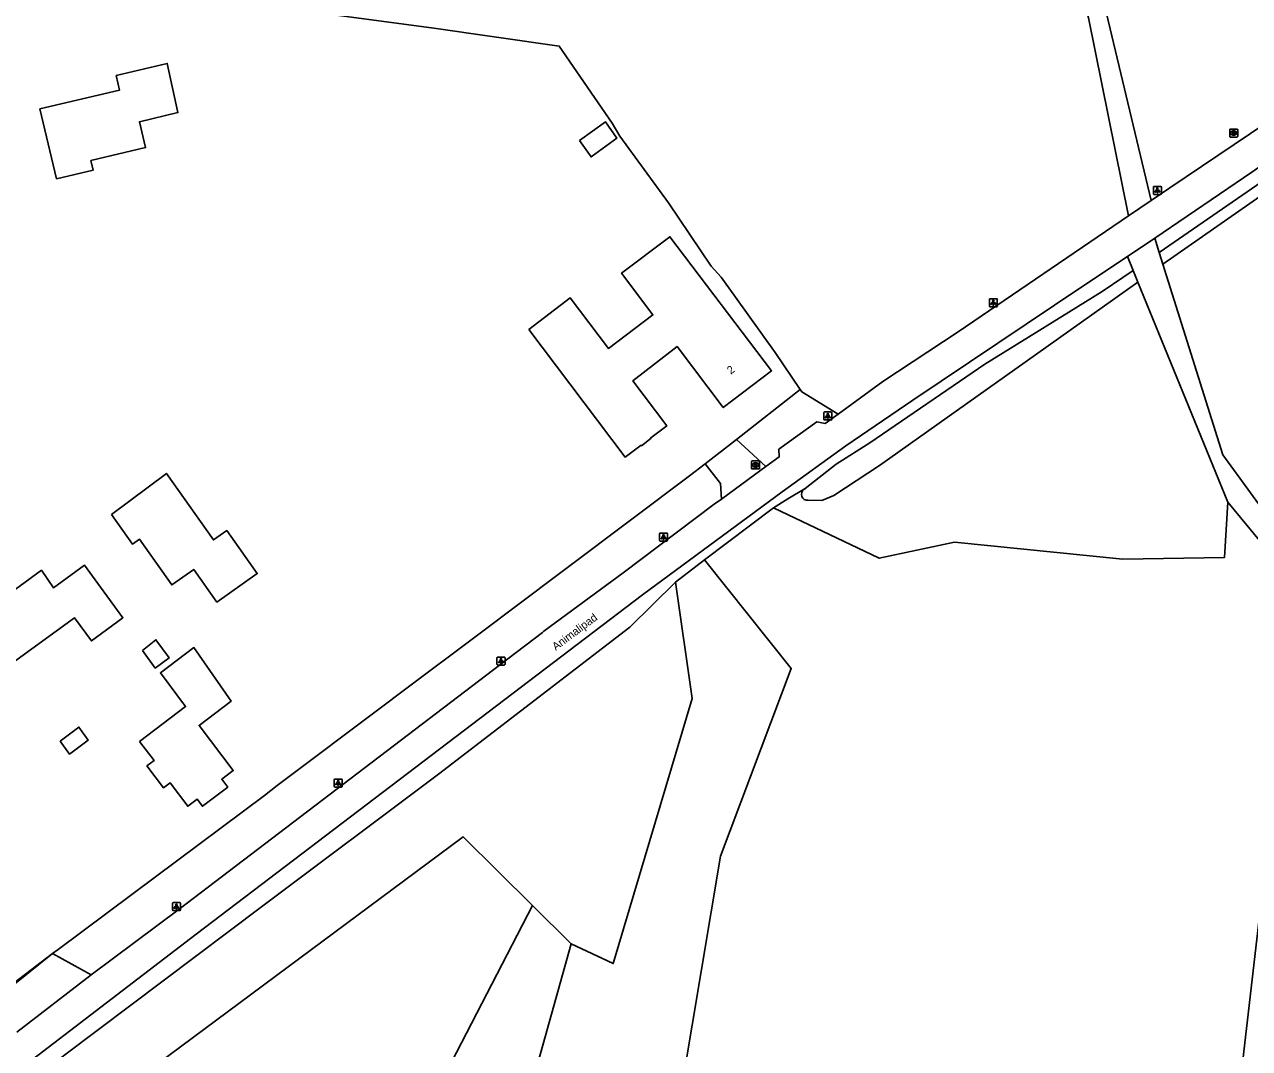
# Model space of a CAD drawing. Extents: x 162157 to 163165, y 378998 to 380775.
# Drawn here: x 162373.7 to 162526.7, y 380232.3 to 380360.2 of the extents above; entities that cross this region are included whole.
import ezdxf

# ---------------------------------------------------------------- set-up
doc = ezdxf.new("R2010")
doc.units = 0
for name, color, linetype in [('IMGEO_Berm_groen', 7, 'Continuous'), ('IMGEO_Brandkraan', 7, 'Continuous'), ('IMGEO_Grasland_overig', 7, 'Continuous'), ('IMGEO_Groenvoorziening', 7, 'Continuous'), ('IMGEO_Hek', 7, 'Continuous'), ('IMGEO_Lichtpunt', 7, 'Continuous'), ('IMGEO_Loofbos', 7, 'Continuous'), ('IMGEO_Muur', 7, 'Continuous'), ('IMGEO_Openbare_ruimte_label', 7, 'Continuous'), ('IMGEO_Pand', 7, 'Continuous'), ('IMGEO_Pand_nummerreeks', 7, 'Continuous'), ('IMGEO_Pand_vergunning_verleend', 7, 'Continuous'), ('IMGEO_Rijbaan_lokaal_gesloten', 7, 'Continuous'), ('IMGEO_Rijbaan_lokaal_halfverhard', 7, 'Continuous'), ('IMGEO_Voetpad_halfverhard', 7, 'Continuous'), ('IMGEO_Voetpad_open', 7, 'Continuous'), ('IMGEO_Waterloop', 7, 'Continuous')]:
    doc.layers.add(name, color=color, linetype=linetype)

msp = doc.modelspace()

# ---------------------------------------------------------------- linework, layer by layer
at = {"layer": 'IMGEO_Berm_groen'}
msp.add_lwpolyline([(162458.72, 380305.32), (162456.79, 380303.81), (162449.57, 380298.41), (162441.18, 380292.1), (162434.83, 380287.34), (162431.27, 380284.67), (162420.34, 380276.48), (162418.94, 380275.41), (162405.25, 380265.15), (162403.66, 380263.89), (162390.04, 380253.73), (162387.11, 380251.53), (162377.9, 380244.68), (162377.2, 380244.15)], dxfattribs=at)
at = {"layer": 'IMGEO_Brandkraan'}
for p, q in [((162524.26, 380346.2), (162524.26, 380347.05)), ((162524.33, 380347.13), (162525.19, 380347.13)), ((162525.19, 380346.13), (162524.33, 380346.13)), ((162524.75, 380346.91), (162524.77, 380346.91)), ((162524.77, 380346.35), (162524.75, 380346.35)), ((162525.26, 380347.05), (162525.26, 380346.2)), ((162464.53, 380304.76), (162464.53, 380305.61)), ((162464.61, 380305.68), (162465.46, 380305.68)), ((162465.02, 380305.46), (162465.05, 380305.46)), ((162465.04, 380304.9), (162465.02, 380304.9)), ((162465.53, 380305.61), (162465.53, 380304.76)), ((162465.46, 380304.68), (162464.61, 380304.68))]:
    msp.add_line(p, q, dxfattribs=at)
for points in [[(162524.26, 380346.2), (162524.26, 380347.05)], [(162524.33, 380347.13), (162525.19, 380347.13)], [(162525.19, 380346.13), (162524.33, 380346.13)], [(162524.61, 380346.83), (162524.61, 380346.43), (162524.82, 380346.43)], [(162524.84, 380346.83), (162524.61, 380346.83)], [(162524.79, 380346.75), (162524.73, 380346.75), (162524.73, 380346.67)], [(162524.73, 380346.67), (162524.79, 380346.67)], [(162524.8, 380346.59), (162524.73, 380346.59), (162524.73, 380346.51)], [(162524.73, 380346.51), (162524.8, 380346.51)], [(162525.26, 380347.05), (162525.26, 380346.2)], [(162464.53, 380304.76), (162464.53, 380305.61)], [(162464.61, 380305.68), (162465.46, 380305.68)], [(162464.88, 380305.38), (162464.88, 380304.98), (162465.09, 380304.98)], [(162465.11, 380305.38), (162464.88, 380305.38)], [(162465.06, 380305.3), (162465.01, 380305.3), (162465.01, 380305.22)], [(162465.01, 380305.22), (162465.06, 380305.22)], [(162465.07, 380305.15), (162465.01, 380305.15), (162465.01, 380305.07)], [(162465.01, 380305.07), (162465.07, 380305.07)], [(162465.53, 380305.61), (162465.53, 380304.76)], [(162465.46, 380304.68), (162464.61, 380304.68)]]:
    msp.add_lwpolyline(points, dxfattribs=at)
for centre, radius, start, end in [((162524.34, 380347.05), 0.0765, 91.552, 178.448), ((162524.34, 380347.05), 0.0765, 91.552, 178.448), ((162524.34, 380346.2), 0.0765, 181.552, 268.448), ((162524.34, 380346.2), 0.0765, 181.552, 268.448), ((162524.79, 380346.71), 0.0379, 267.8285, 90.9355), ((162524.8, 380346.55), 0.0404, 269.8759, 90.5077), ((162524.83, 380346.68), 0.251, 268.6676, 293.5347), ((162524.84, 380346.68), 0.145, 59.4692, 91.5367), ((162524.87, 380346.73), 0.0922, 285.5137, 58.1501), ((162524.87, 380346.54), 0.105, 301.3115, 78.989), ((162525.18, 380347.05), 0.0765, 1.552, 88.448), ((162525.18, 380347.05), 0.0765, 1.552, 88.448), ((162525.18, 380346.2), 0.0765, 271.552, 358.448), ((162525.18, 380346.2), 0.0765, 271.552, 358.448), ((162464.61, 380305.61), 0.0765, 91.552, 178.448), ((162464.61, 380305.61), 0.0765, 91.552, 178.448), ((162465.06, 380305.26), 0.0379, 267.8285, 90.9355), ((162465.07, 380305.11), 0.0404, 269.8759, 90.5077), ((162465.1, 380305.23), 0.251, 268.6676, 293.5347), ((162465.12, 380305.24), 0.145, 59.4692, 91.5367), ((162465.14, 380305.28), 0.0922, 285.5137, 58.1501), ((162465.15, 380305.09), 0.105, 301.3115, 78.989), ((162465.46, 380305.61), 0.0765, 1.552, 88.448), ((162465.46, 380305.61), 0.0765, 1.552, 88.448), ((162464.61, 380304.76), 0.0765, 181.552, 268.448), ((162464.61, 380304.76), 0.0765, 181.552, 268.448), ((162465.46, 380304.76), 0.0765, 271.552, 358.448), ((162465.46, 380304.76), 0.0765, 271.552, 358.448)]:
    msp.add_arc(centre, radius, start, end, dxfattribs=at)
for centre, major_axis, ratio, start_param, end_param in [((162524.75, 380346.63), (-0.387, 0.002), 0.722429, 4.712389, 7.853982), ((162524.77, 380346.63), (-0.39, 0.002), 0.717154, 1.570796, 4.712389), ((162465.02, 380305.18), (-0.387, 0.002), 0.722429, 4.712389, 7.853982), ((162465.04, 380305.18), (-0.39, 0.002), 0.717154, 1.570796, 4.712389)]:
    msp.add_ellipse(centre, major_axis=major_axis, ratio=ratio, start_param=start_param, end_param=end_param, dxfattribs=at)
at = {"layer": 'IMGEO_Grasland_overig'}
msp.add_lwpolyline([(162437.14, 380250.17), (162428.5, 380258.73), (162378.58, 380221.7), (162373.96, 380227.72)], dxfattribs=at)
at = {"layer": 'IMGEO_Groenvoorziening'}
for points in [[(162462.64, 380308.37), (162470.61, 380314.58)], [(162458.66, 380293.31), (162467.25, 380299.83)], [(162458.66, 380293.31), (162469.48, 380279.74), (162460.66, 380256.31), (162453.58, 380214.09), (162455.18, 380204.12), (162493.82, 380200.01), (162523.33, 380208.53)], [(162455.03, 380290.55), (162458.66, 380293.31)], [(162373.96, 380227.72), (162378.73, 380231.49), (162403.3, 380250), (162425.4, 380266.56), (162449.31, 380284.9), (162455.03, 380290.55)], [(162455.03, 380290.55), (162457.1, 380276), (162447.24, 380242.9), (162442, 380245.37)]]:
    msp.add_lwpolyline(points, dxfattribs=at)
at = {"layer": 'IMGEO_Hek'}
for points in [[(162470.61, 380314.58), (162467.48, 380319.24), (162460.73, 380328.61), (162459.47, 380329.99), (162454.14, 380337.89), (162448.06, 380346.22), (162447.12, 380347.84), (162440.5, 380357.48), (162424.53, 380359.77), (162327.51, 380372.72)], [(162470.8, 380314.29), (162470.61, 380314.58)], [(162377.2, 380244.15), (162372.39, 380240.52)], [(162377.9, 380244.68), (162377.2, 380244.15)]]:
    msp.add_lwpolyline(points, dxfattribs=at)
at = {"layer": 'IMGEO_Lichtpunt'}
for p, q in [((162514.73, 380339.87), (162514.73, 380339.06)), ((162514.73, 380339.87), (162514.73, 380339.06)), ((162515.64, 380339.96), (162514.83, 380339.96)), ((162515.64, 380339.96), (162514.83, 380339.96)), ((162514.83, 380338.97), (162515.64, 380338.97)), ((162514.83, 380338.97), (162515.64, 380338.97)), ((162515.73, 380339.06), (162515.73, 380339.87)), ((162515.73, 380339.06), (162515.73, 380339.87)), ((162494.24, 380325.84), (162494.24, 380325.03)), ((162494.24, 380325.84), (162494.24, 380325.03)), ((162495.14, 380325.93), (162494.33, 380325.93)), ((162495.14, 380325.93), (162494.33, 380325.93)), ((162494.33, 380324.94), (162495.14, 380324.94)), ((162494.33, 380324.94), (162495.14, 380324.94)), ((162495.23, 380325.03), (162495.23, 380325.84)), ((162495.23, 380325.03), (162495.23, 380325.84)), ((162473.55, 380311.69), (162473.55, 380310.88)), ((162473.55, 380311.69), (162473.55, 380310.88)), ((162474.45, 380311.79), (162473.65, 380311.79)), ((162474.45, 380311.79), (162473.65, 380311.79)), ((162474.55, 380310.88), (162474.55, 380311.69)), ((162474.55, 380310.88), (162474.55, 380311.69)), ((162473.65, 380310.79), (162474.45, 380310.79)), ((162473.65, 380310.79), (162474.45, 380310.79)), ((162453.03, 380296.57), (162453.03, 380295.76)), ((162453.03, 380296.57), (162453.03, 380295.76)), ((162453.93, 380296.66), (162453.12, 380296.66)), ((162453.93, 380296.66), (162453.12, 380296.66)), ((162453.12, 380295.67), (162453.93, 380295.67)), ((162453.12, 380295.67), (162453.93, 380295.67)), ((162454.03, 380295.76), (162454.03, 380296.57)), ((162454.03, 380295.76), (162454.03, 380296.57)), ((162432.72, 380281.09), (162432.72, 380280.29)), ((162432.72, 380281.09), (162432.72, 380280.29)), ((162433.62, 380281.19), (162432.82, 380281.19)), ((162433.62, 380281.19), (162432.82, 380281.19)), ((162433.72, 380280.29), (162433.72, 380281.09)), ((162433.72, 380280.29), (162433.72, 380281.09)), ((162432.82, 380280.19), (162433.62, 380280.19)), ((162432.82, 380280.19), (162433.62, 380280.19)), ((162412.38, 380265.85), (162412.38, 380265.05)), ((162412.38, 380265.85), (162412.38, 380265.05)), ((162413.28, 380265.95), (162412.47, 380265.95)), ((162413.28, 380265.95), (162412.47, 380265.95)), ((162413.37, 380265.05), (162413.37, 380265.85)), ((162413.37, 380265.05), (162413.37, 380265.85)), ((162412.47, 380264.95), (162413.28, 380264.95)), ((162412.47, 380264.95), (162413.28, 380264.95)), ((162392.17, 380250.42), (162392.17, 380249.62)), ((162392.17, 380250.42), (162392.17, 380249.62)), ((162393.07, 380250.52), (162392.27, 380250.52)), ((162393.07, 380250.52), (162392.27, 380250.52)), ((162393.17, 380249.62), (162393.17, 380250.42)), ((162393.17, 380249.62), (162393.17, 380250.42)), ((162392.27, 380249.52), (162393.07, 380249.52)), ((162392.27, 380249.52), (162393.07, 380249.52))]:
    msp.add_line(p, q, dxfattribs=at)
for points in [[(162515.11, 380339.53), (162515.15, 380339.5), (162514.96, 380339.24), (162514.92, 380339.27), (162515.11, 380339.53)], [(162515.21, 380339.48), (162515.26, 380339.48), (162515.26, 380339.16), (162515.21, 380339.16), (162515.21, 380339.48)], [(162515.32, 380339.5), (162515.36, 380339.53), (162515.54, 380339.27), (162515.51, 380339.24), (162515.32, 380339.5)], [(162494.61, 380325.5), (162494.65, 380325.47), (162494.46, 380325.21), (162494.42, 380325.24), (162494.61, 380325.5)], [(162494.71, 380325.45), (162494.76, 380325.45), (162494.76, 380325.13), (162494.71, 380325.13), (162494.71, 380325.45)], [(162494.82, 380325.47), (162494.86, 380325.5), (162495.05, 380325.24), (162495.01, 380325.21), (162494.82, 380325.47)], [(162473.93, 380311.35), (162473.96, 380311.33), (162473.78, 380311.06), (162473.74, 380311.09), (162473.93, 380311.35)], [(162474.03, 380311.31), (162474.08, 380311.31), (162474.08, 380310.98), (162474.03, 380310.98), (162474.03, 380311.31)], [(162474.14, 380311.33), (162474.18, 380311.35), (162474.36, 380311.09), (162474.32, 380311.06), (162474.14, 380311.33)], [(162453.4, 380296.23), (162453.44, 380296.2), (162453.25, 380295.94), (162453.22, 380295.97), (162453.4, 380296.23)], [(162453.5, 380296.18), (162453.55, 380296.18), (162453.55, 380295.86), (162453.5, 380295.86), (162453.5, 380296.18)], [(162453.61, 380296.2), (162453.65, 380296.23), (162453.84, 380295.97), (162453.8, 380295.94), (162453.61, 380296.2)], [(162433.1, 380280.76), (162433.13, 380280.73), (162432.95, 380280.47), (162432.91, 380280.5), (162433.1, 380280.76)], [(162433.2, 380280.71), (162433.24, 380280.71), (162433.24, 380280.39), (162433.2, 380280.39), (162433.2, 380280.71)], [(162433.31, 380280.73), (162433.35, 380280.76), (162433.53, 380280.49), (162433.49, 380280.47), (162433.31, 380280.73)], [(162412.75, 380265.52), (162412.79, 380265.49), (162412.6, 380265.23), (162412.56, 380265.25), (162412.75, 380265.52)], [(162412.85, 380265.47), (162412.9, 380265.47), (162412.9, 380265.15), (162412.85, 380265.15), (162412.85, 380265.47)], [(162412.96, 380265.49), (162413, 380265.52), (162413.19, 380265.25), (162413.15, 380265.23), (162412.96, 380265.49)], [(162392.55, 380250.09), (162392.58, 380250.06), (162392.4, 380249.8), (162392.36, 380249.82), (162392.55, 380250.09)], [(162392.65, 380250.04), (162392.69, 380250.04), (162392.69, 380249.72), (162392.65, 380249.72), (162392.65, 380250.04)], [(162392.76, 380250.06), (162392.8, 380250.09), (162392.98, 380249.82), (162392.94, 380249.8), (162392.76, 380250.06)]]:
    msp.add_lwpolyline(points, dxfattribs=at)
for centre in [(162515.23, 380339.67), (162494.74, 380325.64), (162474.05, 380311.49), (162453.53, 380296.37), (162433.22, 380280.89), (162412.88, 380265.65), (162392.67, 380250.22)]:
    msp.add_circle(centre, 0.0994, dxfattribs=at)
for centre, start, end in [((162514.83, 380339.87), 90, 180), ((162514.83, 380339.87), 90, 180), ((162514.83, 380339.06), 180, 270), ((162514.83, 380339.06), 180, 270), ((162515.64, 380339.87), 0, 90), ((162515.64, 380339.87), 0, 90), ((162515.64, 380339.06), 270, 0), ((162515.64, 380339.06), 270, 360), ((162494.33, 380325.84), 90, 180), ((162494.33, 380325.84), 90, 180), ((162494.33, 380325.03), 180, 270), ((162494.33, 380325.03), 180, 270), ((162495.14, 380325.84), 0, 90), ((162495.14, 380325.84), 0, 90), ((162495.14, 380325.03), 270, 0), ((162495.14, 380325.03), 270, 360), ((162473.65, 380311.69), 90, 180), ((162473.65, 380311.69), 90, 180), ((162474.45, 380311.69), 0, 90), ((162474.45, 380311.69), 0, 90), ((162473.65, 380310.88), 180, 270), ((162473.65, 380310.88), 180, 270), ((162474.45, 380310.88), 270, 0), ((162474.45, 380310.88), 270, 360), ((162453.12, 380296.57), 90, 180), ((162453.12, 380296.57), 90, 180), ((162453.12, 380295.76), 180, 270), ((162453.12, 380295.76), 180, 270), ((162453.93, 380296.57), 0, 90), ((162453.93, 380296.57), 0, 90), ((162453.93, 380295.76), 270, 0), ((162453.93, 380295.76), 270, 360), ((162432.82, 380281.09), 90, 180), ((162432.82, 380281.09), 90, 180), ((162432.82, 380280.29), 180, 270), ((162432.82, 380280.29), 180, 270), ((162433.62, 380281.09), 0, 90), ((162433.62, 380281.09), 0, 90), ((162433.62, 380280.29), 270, 0), ((162433.62, 380280.29), 270, 360), ((162412.47, 380265.85), 90, 180), ((162412.47, 380265.85), 90, 180), ((162412.47, 380265.05), 180, 270), ((162412.47, 380265.05), 180, 270), ((162413.28, 380265.85), 0, 90), ((162413.28, 380265.85), 0, 90), ((162413.28, 380265.05), 270, 0), ((162413.28, 380265.05), 270, 360), ((162392.27, 380250.42), 90, 180), ((162392.27, 380250.42), 90, 180), ((162393.07, 380250.42), 0, 90), ((162393.07, 380250.42), 0, 90), ((162392.27, 380249.62), 180, 270), ((162392.27, 380249.62), 180, 270), ((162393.07, 380249.62), 270, 0), ((162393.07, 380249.62), 270, 360)]:
    msp.add_arc(centre, 0.0946, start, end, dxfattribs=at)
at = {"layer": 'IMGEO_Loofbos'}
for points in [[(162252.22, 380382.98), (162295.98, 380377.02), (162327.51, 380372.72), (162424.53, 380359.77), (162440.5, 380357.48), (162447.12, 380347.84), (162448.06, 380346.22), (162454.14, 380337.89), (162459.47, 380329.99), (162460.73, 380328.61), (162467.48, 380319.24), (162470.61, 380314.58)], [(162470.61, 380314.58), (162470.8, 380314.29), (162475.36, 380311.53)], [(162467.25, 380299.83), (162469.05, 380300.96), (162471.22, 380302.25)], [(162467.25, 380299.83), (162480.48, 380293.52), (162489.86, 380295.52), (162510.9, 380293.43), (162523.61, 380293.6), (162524.04, 380300.51)], [(162523.33, 380208.53), (162532, 380283.39), (162532.68, 380288.65)], [(162437.14, 380250.17), (162411.8, 380201.13), (162369.04, 380207.47)], [(162442, 380245.37), (162437.14, 380250.17)], [(162523.33, 380208.53), (162520.84, 380187.03), (162441.69, 380197.08), (162430.3, 380203.52), (162442, 380245.37)]]:
    msp.add_lwpolyline(points, dxfattribs=at)
at = {"layer": 'IMGEO_Muur'}
for points in [[(162449.57, 380298.41), (162441.18, 380292.1)], [(162434.83, 380287.34), (162441.18, 380292.1)], [(162420.34, 380276.48), (162431.27, 380284.67)], [(162418.94, 380275.41), (162420.34, 380276.48)], [(162405.25, 380265.15), (162418.94, 380275.41)], [(162403.66, 380263.89), (162405.25, 380265.15)], [(162390.04, 380253.73), (162403.66, 380263.89)], [(162387.11, 380251.53), (162390.04, 380253.73)], [(162377.9, 380244.68), (162387.11, 380251.53)]]:
    msp.add_lwpolyline(points, dxfattribs=at)
at = {"layer": 'IMGEO_Pand'}
for points in [[(162443.04, 380345.68), (162446.27, 380348.03), (162447.71, 380345.99), (162444.48, 380343.64), (162443.04, 380345.68)], [(162436.69, 380322.11), (162441.87, 380326.03), (162446.64, 380319.72), (162452.21, 380323.92), (162448.29, 380329.11), (162454.33, 380333.67), (162467, 380316.93), (162460.98, 380312.34), (162455.22, 380319.96), (162449.68, 380315.67), (162453.92, 380310.05), (162451.93, 380308.57), (162451.98, 380308.51), (162450.79, 380307.57), (162450.73, 380307.65), (162448.72, 380306.16), (162436.69, 380322.11)]]:
    msp.add_lwpolyline(points, dxfattribs=at)
at = {"layer": 'IMGEO_Pand_vergunning_verleend'}
for points in [[(162375.62, 380349.63), (162385.57, 380351.99), (162385.14, 380353.81), (162391.53, 380355.33), (162392.86, 380349.18), (162388.05, 380348.04), (162388.81, 380344.81), (162381.98, 380343.19), (162382.27, 380342), (162377.69, 380340.91), (162375.62, 380349.63)], [(162384.55, 380298.98), (162391.42, 380304.11), (162397.29, 380295.81), (162398.96, 380296.99), (162402.76, 380291.62), (162397.73, 380288.06), (162394.84, 380292.14), (162392.09, 380290.2), (162388.07, 380295.89), (162387.18, 380295.27), (162384.55, 380298.98)], [(162366.96, 380285.57), (162375.8, 380292.03), (162377.31, 380289.82), (162381.19, 380292.66), (162385.98, 380286.09), (162382.04, 380283.21), (162379.93, 380286.1), (162371.4, 380279.87), (162370.38, 380281.26), (162369.53, 380280.64), (162367.31, 380283.68), (162367.98, 380284.17), (162366.96, 380285.57)], [(162388.41, 380282.01), (162390.11, 380283.34), (162391.76, 380281.08), (162390.02, 380279.81), (162388.41, 380282.01)], [(162388.06, 380270.66), (162393.82, 380275.01), (162390.66, 380279.21), (162394.86, 380282.37), (162399.52, 380275.68), (162395.5, 380272.65), (162399.76, 380267.01), (162398.33, 380265.93), (162399.08, 380264.94), (162395.92, 380262.56), (162395.26, 380263.43), (162394.09, 380262.55), (162391.87, 380265.49), (162391.04, 380264.87), (162388.99, 380267.59), (162389.87, 380268.26), (162388.06, 380270.66)], [(162378.14, 380270.68), (162380.49, 380272.43), (162381.64, 380270.79), (162379.32, 380269.07), (162378.14, 380270.68)]]:
    msp.add_lwpolyline(points, dxfattribs=at)
at = {"layer": 'IMGEO_Rijbaan_lokaal_gesloten'}
for points in [[(162579.4, 380383.4), (162579.24, 380382.24), (162548.92, 380361.42), (162516.8, 380339.8), (162514.47, 380338.22)], [(162514.91, 380333.5), (162527.03, 380341.73), (162550.74, 380358.23), (162569.89, 380371.13), (162588.22, 380383.97)], [(162514.47, 380338.22), (162511.61, 380336.28)], [(162511.61, 380336.28), (162490.34, 380321.82), (162480.92, 380315.59), (162475.36, 380311.53)], [(162511.48, 380331.21), (162514.91, 380333.5)], [(162511.48, 380331.21), (162505.93, 380327.51), (162484.67, 380313.25), (162476.32, 380307.57), (162468.33, 380301.8), (162450.89, 380288.94), (162395.15, 380246.57), (162372.73, 380229.41), (162372.69, 380229.38), (162370.26, 380227.56), (162363.86, 380222.76), (162350.25, 380212.01), (162347.18, 380208.96)], [(162475.36, 380311.53), (162473.74, 380310.35), (162472.69, 380310.55), (162467.94, 380307.14), (162467.98, 380306.19), (162466.32, 380304.97)], [(162466.32, 380304.97), (162465.7, 380304.52), (162460.75, 380300.9)], [(162460.75, 380300.9), (162459.87, 380300.26), (162448.48, 380291.7), (162438.58, 380284.4), (162438.4, 380284.26), (162434.07, 380280.96), (162393, 380249.7), (162382, 380241.49)], [(162382, 380241.49), (162372.73, 380234.33)]]:
    msp.add_lwpolyline(points, dxfattribs=at)
at = {"layer": 'IMGEO_Rijbaan_lokaal_halfverhard'}
for points in [[(162515.46, 380331.72), (162514.91, 380333.5)], [(162512.19, 380329.47), (162511.48, 380331.21)], [(162515.46, 380331.72), (162515.93, 380330.24)], [(162512.79, 380328.01), (162512.19, 380329.47)], [(162515.93, 380330.24), (162523.41, 380306.42), (162530.31, 380296.94), (162534.45, 380289.04), (162537.07, 380273.83), (162541.55, 380264.6), (162539.55, 380252.63), (162539.37, 380250), (162538.94, 380244.05), (162540, 380236.55), (162542.8, 380228.02), (162550.33, 380210.83), (162556.24, 380178.65), (162558.37, 380174.09)], [(162524.04, 380300.51), (162512.79, 380328.01)], [(162532.68, 380288.65), (162530.36, 380292.86), (162524.04, 380300.51)]]:
    msp.add_lwpolyline(points, dxfattribs=at)
at = {"layer": 'IMGEO_Voetpad_halfverhard'}
for points in [[(162511.61, 380336.28), (162506.63, 380361), (162500, 380385.37), (162497.56, 380394.35)], [(162500.64, 380393.93), (162508.88, 380361.55), (162514.47, 380338.22)]]:
    msp.add_lwpolyline(points, dxfattribs=at)
at = {"layer": 'IMGEO_Voetpad_open'}
for points in [[(162458.72, 380305.32), (162462.64, 380308.37)], [(162466.32, 380304.97), (162462.64, 380308.37)], [(162460.75, 380300.9), (162460.66, 380302.88), (162458.72, 380305.32)], [(162372.26, 380240.2), (162377.2, 380244.15)], [(162377.2, 380244.15), (162382, 380241.49)]]:
    msp.add_lwpolyline(points, dxfattribs=at)
at = {"layer": 'IMGEO_Waterloop'}
for points in [[(162582.8, 380376.08), (162582.42, 380376.62), (162569.48, 380368.21), (162532.47, 380343.44), (162515.46, 380331.72)], [(162515.93, 380330.24), (162542.6, 380348.85), (162582.8, 380376.08)], [(162471.22, 380302.25), (162475.11, 380305.26), (162479.3, 380307.95), (162493.69, 380317.77), (162500, 380321.67), (162508.34, 380326.82), (162512.19, 380329.47)], [(162512.79, 380328.01), (162500, 380318.94), (162480.5, 380305.12), (162474.82, 380301.35), (162473.32, 380300.75), (162471.58, 380300.77)], [(162471.07, 380302.12), (162471.22, 380302.25)]]:
    msp.add_lwpolyline(points, dxfattribs=at)
msp.add_arc((162471.53, 380301.52), 0.759, 127.7765, 273.6127, dxfattribs=at)

# ---------------------------------------------------------------- texts
at = {"layer": 'IMGEO_Openbare_ruimte_label'}
msp.add_text('Animalipad', height=1, rotation=36.7438, dxfattribs=at).set_placement((162440.07, 380281.96))
at = {"layer": 'IMGEO_Pand_nummerreeks'}
msp.add_text('2', height=1, rotation=38.4881, dxfattribs=at).set_placement((162461.94, 380316.45))

doc.saveas('drawing.dxf')
